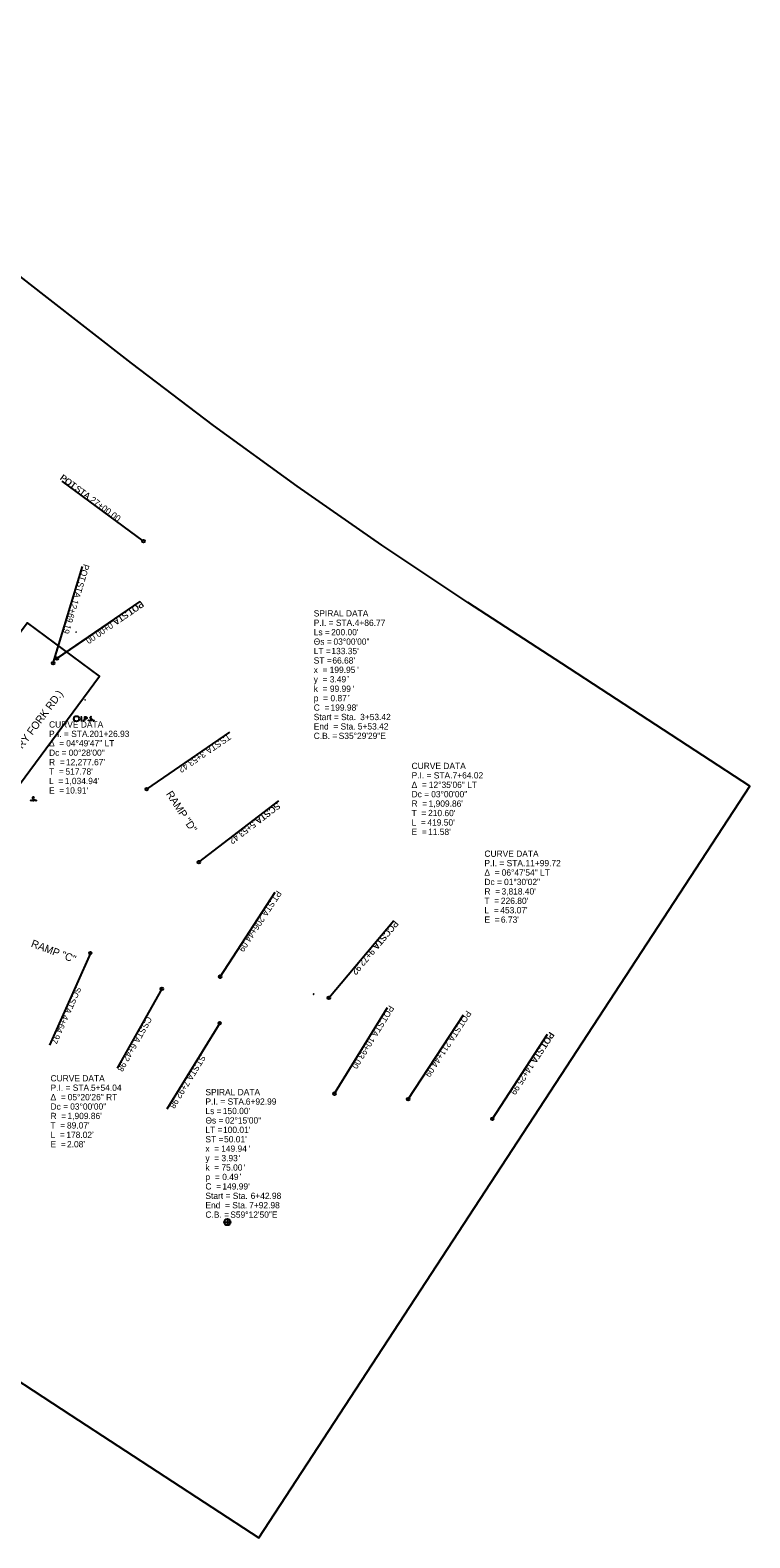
# Model space of a CAD drawing. Extents: x 1323342 to 1326901, y 458396 to 461756.
# Drawn here: x 1325299 to 1326901, y 458396 to 461756 of the extents above; entities that cross this region are included whole.
import ezdxf

# ---------------------------------------------------------------- set-up
doc = ezdxf.new("R2010")
doc.units = 0
for name, color, linetype in [('_CIVIL_CONSTRUCTION', 7, 'Continuous'), ('GE_P_Alignment_500_Cardinal_Points', 7, 'Continuous'), ('GE_P_Alignment_500_Curve_Data', 7, 'Continuous'), ('GE_X_Alignment_500_Cardinal_Points', 7, 'Continuous'), ('GE_X_Alignment_500_Curve_Data', 7, 'Continuous'), ('RD_X_Text', 7, 'Continuous'), ('SH_Named_Boundary', 7, 'Continuous'), ('SV_P_Mon_Cells_Set', 7, 'Continuous')]:
    doc.layers.add(name, color=color, linetype=linetype)

msp = doc.modelspace()

# ---------------------------------------------------------------- linework, layer by layer
at = {"layer": '_CIVIL_CONSTRUCTION'}
for centre in [(1325401.2, 460414.7), (1325421.3, 460263.8), (1325929.8, 459608.2)]:
    msp.add_circle(centre, 0.05, dxfattribs=at)
at = {"layer": 'GE_P_Alignment_500_Cardinal_Points'}
for p, q in [((1325551, 460617.4), (1325370, 460751.1)), ((1325558, 460064.7), (1325743.5, 460192.1)), ((1325674.1, 459901.9), (1325852.6, 460038.8)), ((1325963.8, 459599.6), (1326108.2, 459772.2)), ((1326327.7, 459330.2), (1326450.6, 459518.6))]:
    msp.add_line(p, q, dxfattribs=at)
for centre in [(1325551, 460617.4), (1325558, 460064.7), (1325674.1, 459901.9), (1325963.8, 459599.6), (1326327.7, 459330.2)]:
    msp.add_circle(centre, 3, dxfattribs=at)
at = {"layer": 'GE_X_Alignment_500_Cardinal_Points'}
for p, q in [((1325551, 460617.4), (1325370, 460751.1)), ((1325350, 460345.4), (1325415.3, 460560.7)), ((1325357.9, 460356), (1325543.3, 460483.4)), ((1325558, 460064.7), (1325743.5, 460192.1)), ((1325674.1, 459901.9), (1325852.6, 460038.8)), ((1325721.4, 459647), (1325844.3, 459835.4)), ((1325963.8, 459599.6), (1326108.2, 459772.2)), ((1325432.6, 459699.7), (1325341.3, 459494.1)), ((1325591.7, 459620), (1325492.4, 459442.9)), ((1325976.3, 459386.3), (1326093.9, 459578.1)), ((1325720.5, 459543.3), (1325602.9, 459351.5)), ((1326140.1, 459373.8), (1326263.1, 459562.2)), ((1326327.7, 459330.2), (1326450.6, 459518.6))]:
    msp.add_line(p, q, dxfattribs=at)
for centre in [(1325551, 460617.4), (1325350, 460345.4), (1325357.9, 460356), (1325558, 460064.7), (1325674.1, 459901.9), (1325432.6, 459699.7), (1325721.4, 459647), (1325591.7, 459620), (1325963.8, 459599.6), (1325720.5, 459543.3), (1325976.3, 459386.3), (1326140.1, 459373.8), (1326327.7, 459330.2)]:
    msp.add_circle(centre, 3, dxfattribs=at)
at = {"layer": 'RD_X_Text'}
msp.add_line((1325484.1, 460441.9), (1325355.8, 460354.6), dxfattribs=at)
at = {"layer": 'SH_Named_Boundary'}
for points in [[(1324572.3, 461756.3), (1323342.2, 460179.3), (1323902.4, 459742.4), (1324099.5, 459588.6), (1324299.3, 459432.8), (1324514.7, 459269.4), (1324733.4, 459110.5), (1324955.2, 458956), (1325179.8, 458806.3), (1325389.2, 458669.7), (1325598.5, 458533.1), (1325807.9, 458396.4), (1326900.9, 460071.4), (1326691.5, 460208), (1326482.2, 460344.6), (1326272.8, 460481.2), (1326081.3, 460608.8), (1325892.9, 460740.1), (1325707.1, 460875.1), (1325524.2, 461013.9), (1325329.6, 461165.5), (1325132.5, 461319.3)], [(1324935.7, 459953), (1325096.6, 459834.1), (1325132.3, 459882.4), (1325167.9, 459930.6), (1325203.6, 459978.9), (1325239.2, 460027.2), (1325274.9, 460075.4), (1325310.5, 460123.7), (1325346.2, 460171.9), (1325381.8, 460220.2), (1325417.5, 460268.4), (1325453.2, 460316.7), (1325292.3, 460435.5), (1325256.6, 460387.3), (1325221, 460339), (1325185.3, 460290.8), (1325149.7, 460242.5), (1325114, 460194.3), (1325078.4, 460146), (1325042.7, 460097.8), (1325007.1, 460049.5), (1324971.4, 460001.2)]]:
    msp.add_lwpolyline(points, close=True, dxfattribs=at)
at = {"layer": 'SV_P_Mon_Cells_Set'}
for p, q in [((1325730.7, 459100), (1325744.8, 459100)), ((1325737.7, 459107), (1325737.7, 459092.9))]:
    msp.add_line(p, q, dxfattribs=at)
for points in [[(1325411.7, 460225.7), (1325413.5, 460225.7)], [(1325411.7, 460217.7), (1325413.5, 460217.7)], [(1325412.6, 460217.7), (1325412.6, 460225.7)], [(1325417.4, 460218.8), (1325417.7, 460218.8), (1325417.9, 460218.6), (1325418, 460218.4), (1325418, 460218.1), (1325417.9, 460217.8), (1325417.7, 460217.7), (1325417.4, 460217.7), (1325417.3, 460217.8), (1325417.1, 460218.1), (1325417.1, 460218.4), (1325417.3, 460218.6), (1325417.4, 460218.8)], [(1325420.5, 460217.7), (1325420.5, 460225.7), (1325423.1, 460225.7), (1325423.4, 460225.6), (1325423.8, 460225.5), (1325423.9, 460225.4), (1325424.1, 460225.2), (1325424.3, 460224.9), (1325424.5, 460224.6), (1325424.6, 460224.1), (1325424.6, 460223.4), (1325424.5, 460223.1), (1325424.4, 460222.7), (1325424.2, 460222.3), (1325424, 460222.1), (1325423.8, 460222), (1325423.5, 460221.8), (1325423.1, 460221.8), (1325420.5, 460221.8)], [(1325428.7, 460218.8), (1325428.9, 460218.8), (1325429.1, 460218.6), (1325429.3, 460218.4), (1325429.3, 460218.1), (1325429.1, 460217.8), (1325428.9, 460217.7), (1325428.7, 460217.7), (1325428.5, 460217.8), (1325428.3, 460218.1), (1325428.3, 460218.4), (1325428.5, 460218.6), (1325428.7, 460218.8)], [(1325435.5, 460225.1), (1325435.4, 460225.2), (1325435.2, 460225.4), (1325434.7, 460225.6), (1325434.1, 460225.7), (1325433.7, 460225.7), (1325433.5, 460225.7), (1325432.8, 460225.5), (1325432.2, 460225.1), (1325431.8, 460224.6), (1325431.7, 460224.1), (1325431.7, 460223.7), (1325431.8, 460223.2), (1325432.3, 460222.8), (1325435.3, 460220.9), (1325435.6, 460220.6), (1325435.7, 460220.4), (1325435.8, 460220), (1325435.8, 460219.6), (1325435.7, 460219.3), (1325435.7, 460219), (1325435.6, 460218.7), (1325435.4, 460218.4), (1325435.3, 460218.2), (1325435.2, 460218.1), (1325435, 460217.9), (1325434.8, 460217.8), (1325434.6, 460217.7), (1325434.1, 460217.7), (1325433.4, 460217.7), (1325432.9, 460217.8), (1325432.1, 460218.2), (1325431.7, 460218.6)], [(1325439.6, 460218.8), (1325439.9, 460218.8), (1325440, 460218.6), (1325440.2, 460218.4), (1325440.2, 460218.1), (1325440, 460217.8), (1325439.9, 460217.7), (1325439.6, 460217.7), (1325439.4, 460217.8), (1325439.3, 460218.1), (1325439.3, 460218.4), (1325439.4, 460218.6), (1325439.6, 460218.8)], [(1325300.6, 460040.2), (1325300.8, 460040.2), (1325301, 460040.1), (1325301.2, 460039.9), (1325301.2, 460039.5), (1325301, 460039.3), (1325300.8, 460039.2), (1325300.6, 460039.2), (1325300.4, 460039.3), (1325300.2, 460039.5), (1325300.2, 460039.9), (1325300.4, 460040.1), (1325300.6, 460040.2)], [(1325307.4, 460046.6), (1325307.3, 460046.7), (1325307.1, 460046.9), (1325306.6, 460047), (1325306, 460047.2), (1325305.6, 460047.2), (1325305.4, 460047.2), (1325304.7, 460047), (1325304.1, 460046.6), (1325303.7, 460046.1), (1325303.6, 460045.6), (1325303.6, 460045.2), (1325303.7, 460044.7), (1325304.1, 460044.3), (1325307.2, 460042.4), (1325307.5, 460042.1), (1325307.6, 460041.9), (1325307.7, 460041.5), (1325307.7, 460041.1), (1325307.6, 460040.7), (1325307.6, 460040.5), (1325307.5, 460040.2), (1325307.3, 460039.9), (1325307.2, 460039.7), (1325307.1, 460039.5), (1325306.9, 460039.4), (1325306.7, 460039.3), (1325306.5, 460039.2), (1325306, 460039.2), (1325305.2, 460039.2), (1325304.8, 460039.3), (1325304, 460039.7), (1325303.6, 460040.1)], [(1325311.5, 460040.2), (1325311.7, 460040.2), (1325311.9, 460040.1), (1325312.1, 460039.9), (1325312.1, 460039.5), (1325311.9, 460039.3), (1325311.7, 460039.2), (1325311.5, 460039.2), (1325311.3, 460039.3), (1325311.1, 460039.5), (1325311.1, 460039.9), (1325311.3, 460040.1), (1325311.5, 460040.2)]]:
    msp.add_lwpolyline(points, dxfattribs=at)
for centre, radius in [((1325401.7, 460221.7), 6), ((1325737.7, 459100), 7.05)]:
    msp.add_circle(centre, radius, dxfattribs=at)

# ---------------------------------------------------------------- texts
at = {"layer": 'GE_P_Alignment_500_Cardinal_Points'}
for s, rotation, p in [('POT', 323.5406, (1325363.4, 460756.3)), (' STA. ', 323.5406, (1325392.4, 460734.9)), ('27+00.00', 323.5406, (1325430.4, 460706.8)), ('POT', 214.4914, (1325545.8, 460484.9)), ('0+00.00', 214.4914, (1325477.1, 460437.7)), (' STA. ', 214.4914, (1325516.1, 460464.5)), (' STA. ', 214.4914, (1325722.2, 460177.3)), ('TS', 214.4914, (1325739.3, 460189)), ('3+53.42', 214.4914, (1325683.3, 460150.5)), ('SC', 217.4914, (1325849, 460035.8)), (' STA. ', 217.4914, (1325831.9, 460022.7)), ('5+53.42', 217.4914, (1325794.4, 459993.9)), ('PCC', 230.0764, (1326109.4, 459773.4)), (' STA. ', 230.0764, (1326087.3, 459747)), ('9+72.92', 230.0764, (1326057, 459710.7)), ('POT', 236.8748, (1326455.3, 459525.4)), (' STA. ', 236.8748, (1326435.6, 459495.2)), ('14+25.99', 236.8748, (1326409.8, 459455.7))]:
    msp.add_text(s, height=14, rotation=rotation, dxfattribs=at).set_placement(p)
at = {"layer": 'GE_P_Alignment_500_Curve_Data'}
for s, p in [('SPIRAL DATA', (1325929.9, 460449.7)), ('P.I. = STA. ', (1325929.9, 460428.7)), ('4+86.77', (1326021.2, 460428.7)), ('Ls = ', (1325929.9, 460407.7)), ("200.00'", (1325968.7, 460407.7)), ('Θs = ', (1325929.9, 460386.7)), ('LT = ', (1325929.9, 460365.7)), ("133.35'", (1325969.2, 460365.7)), ('03°00\'00"', (1325973.9, 460386.7)), ('ST = ', (1325929.9, 460344.7)), ('199.95', (1325965.4, 460323.7)), ("66.68'", (1325971.4, 460344.7)), ("'", (1326026.8, 460323.7)), ('y  = ', (1325929.9, 460302.7)), ('x  = ', (1325929.9, 460323.7)), ('3.49', (1325965.7, 460302.7)), ("'", (1326004.8, 460302.7)), ('p  = ', (1325929.9, 460260.7)), ('k  = ', (1325929.9, 460281.7)), ('99.99', (1325965.9, 460281.7)), ('0.87', (1325967.2, 460260.7)), ("'", (1326006.3, 460260.7)), ("'", (1326016.1, 460281.7)), ('C  = ', (1325929.9, 460239.7)), ("199.98'", (1325967.4, 460239.7)), ('Start = Sta. ', (1325929.9, 460218.7)), ('End  = Sta. ', (1325929.9, 460197.7)), ('5+53.42', (1326028.1, 460197.7)), ('3+53.42', (1326033.2, 460218.7)), ('C.B. = ', (1325929.9, 460176.7)), ('S35°29\'29"E', (1325985.5, 460176.7)), ('CURVE DATA', (1326147.8, 460109.7)), ('P.I. = STA. ', (1326147.8, 460088.7)), ('7+64.02', (1326239.1, 460088.7)), ('Δ  = ', (1326147.8, 460067.7)), ('12°35\'06" LT', (1326186.2, 460067.7)), ('Dc = ', (1326147.8, 460046.7)), ('R  = ', (1326147.8, 460025.7)), ("1,909.86'", (1326185.7, 460025.7)), ('03°00\'00"', (1326191.5, 460046.7)), ('T  = ', (1326147.8, 460004.7)), ("210.60'", (1326184.5, 460004.7)), ('L  = ', (1326147.8, 459983.7)), ('E  = ', (1326147.8, 459962.7)), ("419.50'", (1326183, 459983.7)), ("11.58'", (1326184.5, 459962.7)), ('CURVE DATA', (1326310, 459914.1)), ('P.I. = STA. ', (1326310, 459893.1)), ('11+99.72', (1326401.4, 459893.1)), ('Δ  = ', (1326310, 459872.1)), ('Dc = ', (1326310, 459851.1)), ('06°47\'54" LT', (1326348.4, 459872.1)), ('01°30\'02"', (1326353.7, 459851.1)), ('R  = ', (1326310, 459830.1)), ("3,818.40'", (1326348, 459830.1)), ('T  = ', (1326310, 459809.1)), ('L  = ', (1326310, 459788.1)), ("453.07'", (1326345.3, 459788.1)), ("226.80'", (1326346.7, 459809.1)), ('E  = ', (1326310, 459767.1)), ("6.73'", (1326346.7, 459767.1))]:
    msp.add_text(s, height=14, dxfattribs=at).set_placement(p)
at = {"layer": 'GE_X_Alignment_500_Cardinal_Points'}
for s, rotation, p in [('POT', 323.5406, (1325364.2, 460755.7)), (' STA. ', 323.5406, (1325392.8, 460734.5)), ('27+00.00', 323.5406, (1325430.3, 460706.8)), ('POT', 253.1349, (1325417.6, 460567.5)), (' STA. ', 253.1349, (1325407.2, 460533.4)), ('12+69.19', 253.1349, (1325393.7, 460488.8)), ('POT', 214.4914, (1325544.9, 460484.3)), ('0+00.00', 214.4914, (1325477.1, 460437.7)), (' STA. ', 214.4914, (1325515.5, 460464.1)), ('SC', 217.4914, (1325848.5, 460035.4)), (' STA. ', 217.4914, (1325831.2, 460022.2)), ('5+53.42', 217.4914, (1325794.2, 459993.8)), ('PT', 236.873, (1325847.7, 459840.2)), (' STA. ', 236.873, (1325835.8, 459822)), ('206+44.09', 236.873, (1325810.3, 459783)), ('PCC', 230.0764, (1326109.1, 459773)), (' STA. ', 230.0764, (1326086.7, 459746.3)), ('9+72.92', 230.0764, (1326056.8, 459710.5)), (' STA. ', 246.0544, (1325391.4, 459606.4)), ('SC', 246.0544, (1325400.2, 459626.4)), ('POT', 238.4639, (1326098, 459584.3)), ('POT', 236.873, (1326270.2, 459572.8)), ('4+64.97', 246.0544, (1325372.4, 459563.8)), (' STA. ', 240.7139, (1325547.9, 459540.7)), ('CS', 240.7139, (1325558.6, 459559.7)), (' STA. ', 238.4639, (1326079.3, 459554)), (' STA. ', 236.873, (1326250.7, 459542.9)), ('6+42.98', 240.7139, (1325525.1, 459500)), ('10+93.00', 238.4639, (1326054.9, 459514.2)), ('211+44.09', 236.873, (1326225.2, 459503.9)), ('POT', 236.8748, (1326454.7, 459524.5)), ('ST', 238.4639, (1325678.4, 459474.3)), (' STA. ', 236.8748, (1326435.2, 459494.7)), (' STA. ', 238.4639, (1325667.7, 459456.8)), ('14+25.99', 236.8748, (1326409.8, 459455.6)), ('7+92.98', 238.4639, (1325643.3, 459417))]:
    msp.add_text(s, height=14, rotation=rotation, dxfattribs=at).set_placement(p)
at = {"layer": 'GE_X_Alignment_500_Curve_Data'}
for s, p in [('CURVE DATA', (1325340.6, 460202.1)), ('Δ  = ', (1325340.6, 460160.1)), ('P.I. = STA. ', (1325340.6, 460181.1)), ('04°49\'47" LT', (1325378.8, 460160.1)), ('201+26.93', (1325430.5, 460181.1)), ('Dc = ', (1325340.6, 460139.1)), ('00°28\'00"', (1325384.3, 460139.1)), ('T  = ', (1325340.6, 460097.1)), ('R  = ', (1325340.6, 460118.1)), ("517.78'", (1325377.2, 460097.1)), ("12,277.67'", (1325378.3, 460118.1)), ('L  = ', (1325340.6, 460076.1)), ('E  = ', (1325340.6, 460055.1)), ("1,034.94'", (1325375.8, 460076.1)), ("10.91'", (1325377.3, 460055.1)), ('CURVE DATA', (1325343.9, 459413.6)), ('P.I. = STA. ', (1325343.9, 459392.6)), ('5+54.04', (1325433.9, 459392.6)), ('SPIRAL DATA', (1325688.8, 459382.7)), ('Δ  = ', (1325343.9, 459371.6)), ('Dc = ', (1325343.9, 459350.6)), ('05°20\'26" RT', (1325382.2, 459371.6)), ('03°00\'00"', (1325387.7, 459350.6)), ('P.I. = STA. ', (1325688.8, 459361.7)), ('6+92.99', (1325778.7, 459361.7)), ('R  = ', (1325343.9, 459329.6)), ("1,909.86'", (1325381.6, 459329.6)), ('Θs = ', (1325688.8, 459319.7)), ('Ls = ', (1325688.8, 459340.7)), ("150.00'", (1325727.5, 459340.7)), ('02°15\'00"', (1325732.7, 459319.7)), ('T  = ', (1325343.9, 459308.6)), ('L  = ', (1325343.9, 459287.6)), ("178.02'", (1325379.1, 459287.6)), ("89.07'", (1325380.5, 459308.6)), ('LT = ', (1325688.8, 459298.7)), ("100.01'", (1325728, 459298.7)), ('E  = ', (1325343.9, 459266.6)), ("2.08'", (1325380.6, 459266.6)), ('x  = ', (1325688.8, 459256.7)), ('ST = ', (1325688.8, 459277.7)), ('149.94', (1325723.9, 459256.7)), ("50.01'", (1325730.3, 459277.7)), ("'", (1325785.2, 459256.7)), ('y  = ', (1325688.8, 459235.7)), ('k  = ', (1325688.8, 459214.7)), ('3.93', (1325724.4, 459235.7)), ('75.00', (1325724.4, 459214.7)), ("'", (1325763.4, 459235.7)), ("'", (1325774.5, 459214.7)), ('p  = ', (1325688.8, 459193.7)), ('0.49', (1325726.2, 459193.7)), ("'", (1325765.1, 459193.7)), ('Start = Sta. ', (1325688.8, 459151.7)), ('C  = ', (1325688.8, 459172.7)), ("149.99'", (1325726.5, 459172.7)), ('6+42.98', (1325789.5, 459151.7)), ('End  = Sta. ', (1325688.8, 459130.7)), ('7+92.98', (1325786.1, 459130.7)), ('C.B. = ', (1325688.8, 459109.7)), ('S59°12\'50"E', (1325744.1, 459109.7))]:
    msp.add_text(s, height=14, dxfattribs=at).set_placement(p)
at = {"layer": 'RD_X_Text'}
for s, rotation, p in [('C.R.14 (DRY FORK RD.)', 53.4743, (1325220.9, 460072.4)), ('RAMP "D"', 303.1082, (1325600.2, 460054.1)), ('RAMP "C"', 339.163, (1325299.1, 459714.3))]:
    msp.add_text(s, height=17, rotation=rotation, dxfattribs=at).set_placement(p)

doc.saveas('drawing.dxf')
